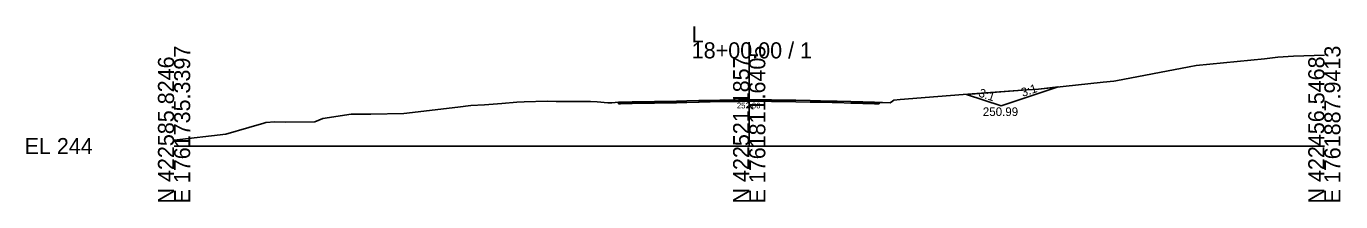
# Model space of a CAD drawing. Extents: x -26 to 3203, y -11010 to 4024.
# Drawn here: x -25.7 to 202.8, y -8509.7 to -8479.1 of the extents above; entities that cross this region are included whole.
import ezdxf

# ---------------------------------------------------------------- set-up
doc = ezdxf.new("R2010")
doc.units = 0
for name, color, linetype in [('Default', 7, 'Continuous'), ('Exist Cross Section Cell', 7, 'Continuous'), ('Exist XS Center Line Elevation Label', 7, 'Continuous'), ('Exist XS Ground Line', 7, 'Continuous'), ('Prop CMT Ditch DDE', 7, 'Continuous'), ('Prop CMT Pvmt Course 1', 7, 'Continuous'), ('Prop XS Ditch Standard Text', 7, 'Continuous'), ('Prop XS Side Slope Text', 7, 'Continuous'), ('Scratch_Level_0', 7, 'Continuous')]:
    doc.layers.add(name, color=color, linetype=linetype)

msp = doc.modelspace()

# ---------------------------------------------------------------- linework, layer by layer
at = {"layer": 'Exist Cross Section Cell'}
for p, q in [((100, -8500), (100, -8481.93)), ((0, -8500), (100, -8500)), ((100, -8500), (200, -8500))]:
    msp.add_line(p, q, dxfattribs=at)
at = {"layer": 'Exist XS Ground Line'}
msp.add_lwpolyline([(0, -8498.98), (9.01, -8497.91), (12.98, -8496.79), (15.61, -8496), (15.93, -8495.89), (17.54, -8495.76), (19.41, -8495.84), (24.48, -8495.77), (25.87, -8495.21), (30.82, -8494.45), (34.22, -8494.46), (39.95, -8494.31), (49.32, -8493.21), (51.59, -8492.92), (53.97, -8492.79), (57, -8492.59), (59.6, -8492.33), (60.88, -8492.29), (64.88, -8492.2), (66.42, -8492.23), (71.47, -8492.22), (71.55, -8492.21), (72.39, -8492.22), (73.54, -8492.29), (75.4, -8492.47), (76.14, -8492.44), (77.3, -8492.38), (77.58, -8492.37), (77.69, -8492.36), (78.61, -8492.34), (79.66, -8492.32), (81.72, -8492.29), (83.53, -8492.25), (84.29, -8492.24), (85.01, -8492.22), (86.14, -8492.21), (87.36, -8492.19), (88.29, -8492.17), (88.93, -8492.15), (89.15, -8492.14), (91.22, -8492.08), (91.38, -8492.07), (91.52, -8492.07), (93.21, -8492.04), (94.89, -8492.01), (94.97, -8492.01), (95.07, -8492), (96.7, -8491.98), (98.14, -8491.96), (98.5, -8491.96), (99.03, -8491.95), (100.24, -8491.94), (101.2, -8491.94), (101.41, -8491.93), (102.08, -8491.94), (102.89, -8491.95), (103.9, -8491.97), (104.83, -8491.98), (105.73, -8491.99), (106.7, -8492), (108.08, -8492.03), (110.6, -8492.09), (110.91, -8492.1), (111.09, -8492.11), (112.33, -8492.13), (112.39, -8492.13), (114.44, -8492.15), (114.64, -8492.15), (115.29, -8492.17), (117.65, -8492.25), (118.34, -8492.27), (119.73, -8492.31), (121.01, -8492.35), (121.81, -8492.37), (122.62, -8492.39), (123.2, -8492.41), (124.52, -8492.45), (124.89, -8492.2), (125.17, -8492), (126.23, -8491.86), (132.78, -8491.36), (137.17, -8491.04), (148.25, -8490.2), (150.27, -8490.07), (161.51, -8488.87), (163.38, -8488.68), (163.72, -8488.63), (176.49, -8486.2), (177.72, -8485.98), (189.59, -8484.81), (191.92, -8484.54), (194.66, -8484.37), (200, -8484.15)], dxfattribs=at)
msp.add_lwpolyline([(0, -8498.98), (9.01, -8497.91), (12.98, -8496.79), (15.61, -8496), (15.93, -8495.89), (17.54, -8495.76), (19.41, -8495.84), (24.48, -8495.77), (25.87, -8495.21), (30.82, -8494.45), (34.22, -8494.46), (39.95, -8494.31), (49.32, -8493.21), (51.59, -8492.92), (53.97, -8492.79), (57, -8492.59), (59.6, -8492.33), (60.88, -8492.29), (64.88, -8492.2), (66.42, -8492.23), (71.47, -8492.22), (71.55, -8492.21), (72.39, -8492.22), (73.54, -8492.29), (75.4, -8492.47), (76.14, -8492.44), (77.3, -8492.38), (77.58, -8492.37), (77.69, -8492.36), (78.61, -8492.34), (79.66, -8492.32), (81.72, -8492.29), (83.53, -8492.25), (84.29, -8492.24), (85.01, -8492.22), (86.14, -8492.21), (87.36, -8492.19), (88.29, -8492.17), (88.93, -8492.15), (89.15, -8492.14), (91.22, -8492.08), (91.38, -8492.07), (91.52, -8492.07), (93.21, -8492.04), (94.89, -8492.01), (94.97, -8492.01), (95.07, -8492), (96.7, -8491.98), (98.14, -8491.96), (98.5, -8491.96), (99.03, -8491.95), (100.24, -8491.94), (101.2, -8491.94), (101.41, -8491.93), (102.08, -8491.94), (102.89, -8491.95), (103.9, -8491.97), (104.83, -8491.98), (105.73, -8491.99), (106.7, -8492), (108.08, -8492.03), (110.6, -8492.09), (110.91, -8492.1), (111.09, -8492.11), (112.33, -8492.13), (112.39, -8492.13), (114.44, -8492.15), (114.64, -8492.15), (115.29, -8492.17), (117.65, -8492.25), (118.34, -8492.27), (119.73, -8492.31), (121.01, -8492.35), (121.81, -8492.37), (122.62, -8492.39), (123.2, -8492.41), (124.52, -8492.45), (124.89, -8492.2), (125.17, -8492), (126.23, -8491.86), (132.78, -8491.36), (137.17, -8491.04), (148.25, -8490.2), (150.27, -8490.07), (161.51, -8488.87), (163.38, -8488.68), (163.72, -8488.63), (176.49, -8486.2), (177.72, -8485.98), (189.59, -8484.81), (191.92, -8484.54), (194.66, -8484.37), (200, -8484.15)], dxfattribs=at)
msp.add_lwpolyline([(0, -8498.98), (9.01, -8497.91), (12.98, -8496.79), (15.61, -8496), (15.93, -8495.89), (17.54, -8495.76), (19.41, -8495.84), (24.48, -8495.77), (25.87, -8495.21), (30.82, -8494.45), (34.22, -8494.46), (39.95, -8494.31), (49.32, -8493.21), (51.59, -8492.92), (53.97, -8492.79), (57, -8492.59), (59.6, -8492.33), (60.88, -8492.29), (64.88, -8492.2), (66.42, -8492.23), (71.47, -8492.22), (71.55, -8492.21), (72.39, -8492.22), (73.54, -8492.29), (75.4, -8492.47), (76.14, -8492.44), (77.3, -8492.38), (77.58, -8492.37), (77.69, -8492.36), (78.61, -8492.34), (79.66, -8492.32), (81.72, -8492.29), (83.53, -8492.25), (84.29, -8492.24), (85.01, -8492.22), (86.14, -8492.21), (87.36, -8492.19), (88.29, -8492.17), (88.93, -8492.15), (89.15, -8492.14), (91.22, -8492.08), (91.38, -8492.07), (91.52, -8492.07), (93.21, -8492.04), (94.89, -8492.01), (94.97, -8492.01), (95.07, -8492), (96.7, -8491.98), (98.14, -8491.96), (98.5, -8491.96), (99.03, -8491.95), (100.24, -8491.94), (101.2, -8491.94), (101.41, -8491.93), (102.08, -8491.94), (102.89, -8491.95), (103.9, -8491.97), (104.83, -8491.98), (105.73, -8491.99), (106.7, -8492), (108.08, -8492.03), (110.6, -8492.09), (110.91, -8492.1), (111.09, -8492.11), (112.33, -8492.13), (112.39, -8492.13), (114.44, -8492.15), (114.64, -8492.15), (115.29, -8492.17), (117.65, -8492.25), (118.34, -8492.27), (119.73, -8492.31), (121.01, -8492.35), (121.81, -8492.37), (122.62, -8492.39), (123.2, -8492.41), (124.52, -8492.45), (124.89, -8492.2), (125.17, -8492), (126.23, -8491.86), (132.78, -8491.36), (137.17, -8491.04), (148.25, -8490.2), (150.27, -8490.07), (161.51, -8488.87), (163.38, -8488.68), (163.72, -8488.63), (176.49, -8486.2), (177.72, -8485.98), (189.59, -8484.81), (191.92, -8484.54), (194.66, -8484.37), (200, -8484.15)], dxfattribs=at)
msp.add_lwpolyline([(0, -8498.98), (9.01, -8497.91), (12.98, -8496.79), (15.61, -8496), (15.93, -8495.89), (17.54, -8495.76), (19.41, -8495.84), (24.48, -8495.77), (25.87, -8495.21), (30.82, -8494.45), (34.22, -8494.46), (39.95, -8494.31), (49.32, -8493.21), (51.59, -8492.92), (53.97, -8492.79), (57, -8492.59), (59.6, -8492.33), (60.88, -8492.29), (64.88, -8492.2), (66.42, -8492.23), (71.47, -8492.22), (71.55, -8492.21), (72.39, -8492.22), (73.54, -8492.29), (75.4, -8492.47), (76.14, -8492.44), (77.3, -8492.38), (77.58, -8492.37), (77.69, -8492.36), (78.61, -8492.34), (79.66, -8492.32), (81.72, -8492.29), (83.53, -8492.25), (84.29, -8492.24), (85.01, -8492.22), (86.14, -8492.21), (87.36, -8492.19), (88.29, -8492.17), (88.93, -8492.15), (89.15, -8492.14), (91.22, -8492.08), (91.38, -8492.07), (91.52, -8492.07), (93.21, -8492.04), (94.89, -8492.01), (94.97, -8492.01), (95.07, -8492), (96.7, -8491.98), (98.14, -8491.96), (98.5, -8491.96), (99.03, -8491.95), (100.24, -8491.94), (101.2, -8491.94), (101.41, -8491.93), (102.08, -8491.94), (102.89, -8491.95), (103.9, -8491.97), (104.83, -8491.98), (105.73, -8491.99), (106.7, -8492), (108.08, -8492.03), (110.6, -8492.09), (110.91, -8492.1), (111.09, -8492.11), (112.33, -8492.13), (112.39, -8492.13), (114.44, -8492.15), (114.64, -8492.15), (115.29, -8492.17), (117.65, -8492.25), (118.34, -8492.27), (119.73, -8492.31), (121.01, -8492.35), (121.81, -8492.37), (122.62, -8492.39), (123.2, -8492.41), (124.52, -8492.45), (124.89, -8492.2), (125.17, -8492), (126.23, -8491.86), (132.78, -8491.36), (137.17, -8491.04), (148.25, -8490.2), (150.27, -8490.07), (161.51, -8488.87), (163.38, -8488.68), (163.72, -8488.63), (176.49, -8486.2), (177.72, -8485.98), (189.59, -8484.81), (191.92, -8484.54), (194.66, -8484.37), (200, -8484.15)], dxfattribs=at)
msp.add_lwpolyline([(0, -8498.98), (9.01, -8497.91), (12.98, -8496.79), (15.61, -8496), (15.93, -8495.89), (17.54, -8495.76), (19.41, -8495.84), (24.48, -8495.77), (25.87, -8495.21), (30.82, -8494.45), (34.22, -8494.46), (39.95, -8494.31), (49.32, -8493.21), (51.59, -8492.92), (53.97, -8492.79), (57, -8492.59), (59.6, -8492.33), (60.88, -8492.29), (64.88, -8492.2), (66.42, -8492.23), (71.47, -8492.22), (71.55, -8492.21), (72.39, -8492.22), (73.54, -8492.29), (75.4, -8492.47), (76.14, -8492.44), (77.3, -8492.38), (77.58, -8492.37), (77.69, -8492.36), (78.61, -8492.34), (79.66, -8492.32), (81.72, -8492.29), (83.53, -8492.25), (84.29, -8492.24), (85.01, -8492.22), (86.14, -8492.21), (87.36, -8492.19), (88.29, -8492.17), (88.93, -8492.15), (89.15, -8492.14), (91.22, -8492.08), (91.38, -8492.07), (91.52, -8492.07), (93.21, -8492.04), (94.89, -8492.01), (94.97, -8492.01), (95.07, -8492), (96.7, -8491.98), (98.14, -8491.96), (98.5, -8491.96), (99.03, -8491.95), (100.24, -8491.94), (101.2, -8491.94), (101.41, -8491.93), (102.08, -8491.94), (102.89, -8491.95), (103.9, -8491.97), (104.83, -8491.98), (105.73, -8491.99), (106.7, -8492), (108.08, -8492.03), (110.6, -8492.09), (110.91, -8492.1), (111.09, -8492.11), (112.33, -8492.13), (112.39, -8492.13), (114.44, -8492.15), (114.64, -8492.15), (115.29, -8492.17), (117.65, -8492.25), (118.34, -8492.27), (119.73, -8492.31), (121.01, -8492.35), (121.81, -8492.37), (122.62, -8492.39), (123.2, -8492.41), (124.52, -8492.45), (124.89, -8492.2), (125.17, -8492), (126.23, -8491.86), (132.78, -8491.36), (137.17, -8491.04), (148.25, -8490.2), (150.27, -8490.07), (161.51, -8488.87), (163.38, -8488.68), (163.72, -8488.63), (176.49, -8486.2), (177.72, -8485.98), (189.59, -8484.81), (191.92, -8484.54), (194.66, -8484.37), (200, -8484.15)], dxfattribs=at)
at = {"layer": 'Prop CMT Ditch DDE'}
msp.add_lwpolyline([(137.78, -8490.99), (143.82, -8493.01), (153.74, -8489.7)], dxfattribs=at)
at = {"layer": 'Prop CMT Pvmt Course 1'}
for points in [[(77.29, -8492.38), (77.3, -8492.38), (77.58, -8492.37), (77.69, -8492.36), (78.61, -8492.34), (79.66, -8492.32), (81.72, -8492.29), (83.53, -8492.25), (84.29, -8492.24), (85.01, -8492.22), (86.14, -8492.21), (87.36, -8492.19), (88.29, -8492.17), (88.93, -8492.15), (89.15, -8492.14), (91.22, -8492.08), (91.38, -8492.07), (91.52, -8492.07), (93.21, -8492.04), (94.89, -8492.01), (94.97, -8492.01), (95.07, -8492), (96.7, -8491.98), (98.14, -8491.96), (98.5, -8491.96), (99.03, -8491.95), (100, -8491.94)], [(100, -8492.19), (99.03, -8492.2), (98.5, -8492.21), (98.14, -8492.21), (96.7, -8492.23), (95.07, -8492.25), (94.97, -8492.26), (94.89, -8492.26), (93.21, -8492.29), (91.52, -8492.32), (91.38, -8492.32), (91.22, -8492.33), (89.15, -8492.39), (88.93, -8492.4), (88.29, -8492.42), (87.36, -8492.44), (86.14, -8492.46), (85.01, -8492.47), (84.29, -8492.49), (83.53, -8492.5), (81.72, -8492.54), (79.66, -8492.57), (78.61, -8492.59), (77.69, -8492.61), (77.58, -8492.62), (77.3, -8492.63), (77.29, -8492.63)], [(100, -8491.94), (100.24, -8491.94), (101.2, -8491.94), (101.41, -8491.93), (102.08, -8491.94), (102.89, -8491.95), (103.9, -8491.97), (104.83, -8491.98), (105.73, -8491.99), (106.7, -8492), (108.08, -8492.03), (110.6, -8492.09), (110.91, -8492.1), (111.09, -8492.11), (112.33, -8492.13), (112.39, -8492.13), (114.44, -8492.15), (114.64, -8492.15), (115.29, -8492.17), (117.65, -8492.25), (118.34, -8492.27), (119.73, -8492.31), (121.01, -8492.35), (121.81, -8492.37), (122.62, -8492.39)], [(100, -8491.94), (100, -8492.19)], [(100, -8492.19), (100, -8491.94)], [(122.62, -8492.64), (121.81, -8492.62), (121.01, -8492.6), (119.73, -8492.56), (118.34, -8492.52), (117.65, -8492.5), (115.29, -8492.42), (114.64, -8492.4), (114.44, -8492.4), (112.39, -8492.38), (112.33, -8492.38), (111.09, -8492.36), (110.91, -8492.35), (110.6, -8492.34), (108.08, -8492.28), (106.7, -8492.25), (105.73, -8492.24), (104.83, -8492.23), (103.9, -8492.22), (102.89, -8492.2), (102.08, -8492.19), (101.41, -8492.18), (101.2, -8492.19), (100.24, -8492.19), (100, -8492.19)], [(77.29, -8492.63), (77.29, -8492.38)], [(122.62, -8492.39), (122.62, -8492.64)]]:
    msp.add_lwpolyline(points, dxfattribs=at)
at = {"layer": 'Scratch_Level_0'}
msp.add_line((153.74, -8489.7), (150.27, -8490.07), dxfattribs=at)
for points in [[(137.78, -8490.99), (143.82, -8493.01), (153.74, -8489.7)], [(153.74, -8489.7), (153.74, -8489.7)], [(150.27, -8490.07), (148.25, -8490.2), (137.78, -8490.99)], [(137.78, -8490.99), (137.78, -8490.99)]]:
    msp.add_lwpolyline(points, dxfattribs=at)

# ---------------------------------------------------------------- texts
at = {"layer": 'Default'}
msp.add_text('-', height=0.0001, dxfattribs=at).set_placement((0, -8500))
at = {"layer": 'Exist Cross Section Cell'}
for s, p in [('L', (90, -8481.93)), ('18+00.00 / 1', (90, -8484.73)), ('EL 244', (-26, -8501.4))]:
    msp.add_text(s, height=2.8, dxfattribs=at).set_placement(p)
for s, p in [('E 1761735.3397', (2.8, -8510)), ('E 1761811.6405', (102.8, -8510)), ('E 1761887.9413', (202.8, -8510)), ('N 422585.8246', (0, -8510)), ('N 422521.1857', (100, -8510)), ('N 422456.5468', (200, -8510))]:
    msp.add_text(s, height=2.8, rotation=90, dxfattribs=at).set_placement(p)
at = {"layer": 'Exist XS Center Line Elevation Label'}
msp.add_text('252.06', height=1, dxfattribs=at).set_placement((97.86, -8493.44))
at = {"layer": 'Prop XS Ditch Standard Text'}
msp.add_text('250.99', height=1.5, dxfattribs=at).set_placement((140.62, -8494.76))
msp.add_text('250.99', height=1.5, dxfattribs=at).set_placement((140.62, -8494.76))
msp.add_text('250.99', height=1.5, dxfattribs=at).set_placement((140.62, -8494.76))
at = {"layer": 'Prop XS Side Slope Text'}
for rotation, p in [(18.4349, (147.56, -8491.44)), (341.5651, (139.77, -8491.34))]:
    msp.add_text('3:1', height=1.5, rotation=rotation, dxfattribs=at).set_placement(p)
at = {"layer": 'Scratch_Level_0'}
for s, p in [('RT_DD_Boundary Out', (153.57, -8489.71)), ('Exterior Boundary', (153.58, -8489.71)), ('PV1_PGL', (99.95, -8491.95)), ('RT_SS_Fill_Point', (137.66, -8491)), ('Exterior Boundary', (77.13, -8492.39)), ('LT_Res Edge', (77.19, -8492.39)), ('RT_Res_Edge', (122.52, -8492.4)), ('RT_DD_Base In', (143.71, -8493.02))]:
    msp.add_text(s, height=0.02, dxfattribs=at).set_placement(p)

doc.saveas('drawing.dxf')
